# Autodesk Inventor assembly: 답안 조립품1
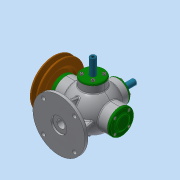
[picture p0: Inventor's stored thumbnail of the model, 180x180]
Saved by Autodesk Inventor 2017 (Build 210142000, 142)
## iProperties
Part Number: 답안 조립품1
Material: 일반
Document SubType Name: Assembly
Designer: MRC
Mass: 3778.23 g
Surface Area: 2410.88 cm^2
Volume: 904.616 cm^3
Density: 4.17662 g/cm^3
Author: MRC
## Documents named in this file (17)
- C:\Users\MRC\Desktop\600911V1005\답안 조립품1.iam
- C:\Users\MRC\Desktop\600911V1005\본체.ipt
- C:\Users\MRC\Desktop\600911V1005\V-벨트풀리.ipt
- C:\Users\MRC\Desktop\600911V1005\너트 M8x1.ipt
- C:\Users\MRC\Desktop\600911V1005\뒤커버.ipt
- C:\Users\MRC\Desktop\600911V1005\베어링 6202.ipt
- C:\Users\MRC\Desktop\600911V1005\본체커버.ipt
- C:\Users\MRC\Desktop\600911V1005\볼트 M4.ipt
- C:\Users\MRC\Desktop\600911V1005\스프링1.ipt
- C:\Users\MRC\Desktop\600911V1005\스프링2.ipt
- C:\Users\MRC\Desktop\600911V1005\슬라이드 커버.ipt
- C:\Users\MRC\Desktop\600911V1005\슬라이드.ipt
- C:\Users\MRC\Desktop\600911V1005\앞커버.ipt
- C:\Users\MRC\Desktop\600911V1005\오일 실.ipt
- C:\Users\MRC\Desktop\600911V1005\와셔 8x17.ipt
- C:\Users\MRC\Desktop\600911V1005\축.ipt
- C:\Users\MRC\Desktop\600911V1005\키 4x4.ipt
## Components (1 placed, 1 different names)
1. V-벨트풀리:1
